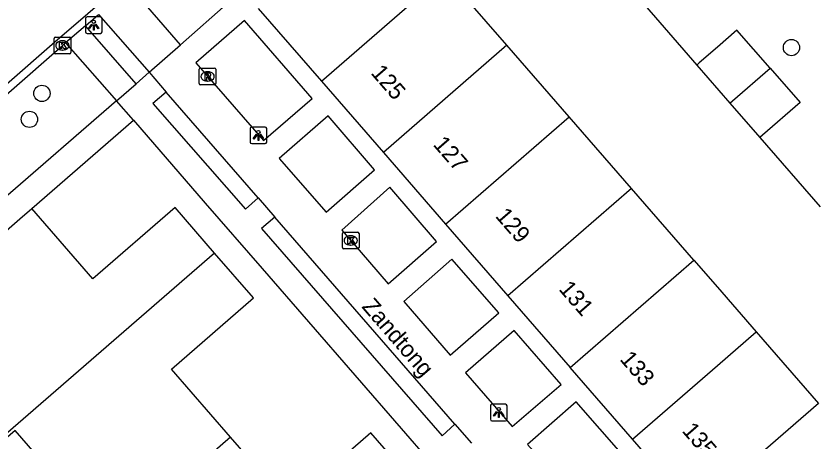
# Model space of a CAD drawing. Extents: x 155888 to 156864, y 383882 to 384671.
# Drawn here: x 156457.85 to 156505.75, y 384320.29 to 384345.85 of the extents above; entities that cross this region are included whole.
import ezdxf

# ---------------------------------------------------------------- set-up
doc = ezdxf.new("R2010")
doc.units = 0
for name, color, linetype in [('IMGEO_Boom', 7, 'Continuous'), ('IMGEO_Kolk', 7, 'Continuous'), ('IMGEO_Lichtpunt', 7, 'Continuous'), ('IMGEO_Muur', 7, 'Continuous'), ('IMGEO_Openbare_ruimte_label', 7, 'Continuous'), ('IMGEO_Pand', 7, 'Continuous'), ('IMGEO_Pand_nummerreeks', 7, 'Continuous'), ('IMGEO_Rijbaan_lokaal_gesloten', 7, 'Continuous'), ('IMGEO_Rijbaan_lokaal_open', 7, 'Continuous'), ('IMGEO_Rioolput', 7, 'Continuous'), ('IMGEO_Voetpad_open', 7, 'Continuous')]:
    doc.layers.add(name, color=color, linetype=linetype)

msp = doc.modelspace()

# ---------------------------------------------------------------- linework, layer by layer
at = {"layer": 'IMGEO_Boom'}
for centre in [(156504.451, 384343.944), (156459.411, 384341.19), (156458.663, 384339.629)]:
    msp.add_circle(centre, 0.489, dxfattribs=at)
at = {"layer": 'IMGEO_Kolk'}
for p, q in [((156460.144, 384343.644), (156460.144, 384344.496)), ((156460.219, 384344.57), (156461.071, 384344.57)), ((156461.145, 384344.496), (156461.145, 384343.644)), ((156460.632, 384344.35), (156460.657, 384344.35)), ((156461.071, 384343.57), (156460.219, 384343.57)), ((156460.655, 384343.79), (156460.63, 384343.79)), ((156477.465, 384331.921), (156477.465, 384332.773)), ((156477.54, 384332.847), (156478.392, 384332.847)), ((156477.953, 384332.627), (156477.978, 384332.627)), ((156478.466, 384332.773), (156478.466, 384331.921)), ((156477.976, 384332.067), (156477.951, 384332.067)), ((156478.392, 384331.847), (156477.54, 384331.847))]:
    msp.add_line(p, q, dxfattribs=at)
for points in [[(156460.144, 384343.644), (156460.144, 384344.496)], [(156460.219, 384344.57), (156461.071, 384344.57)], [(156461.145, 384344.496), (156461.145, 384343.644)], [(156460.465, 384344.27), (156460.588, 384344.27), (156460.588, 384344.119), (156460.718, 384344.27), (156460.882, 384344.27), (156460.736, 384344.119), (156460.889, 384343.87), (156460.737, 384343.87), (156460.652, 384344.034), (156460.588, 384343.967), (156460.588, 384343.87), (156460.465, 384343.87), (156460.465, 384344.27)], [(156461.071, 384343.57), (156460.219, 384343.57)], [(156477.465, 384331.921), (156477.465, 384332.773)], [(156477.54, 384332.847), (156478.392, 384332.847)], [(156477.786, 384332.547), (156477.909, 384332.547), (156477.909, 384332.396), (156478.039, 384332.547), (156478.203, 384332.547), (156478.057, 384332.396), (156478.21, 384332.147), (156478.058, 384332.147), (156477.973, 384332.311), (156477.909, 384332.244), (156477.909, 384332.147), (156477.786, 384332.147), (156477.786, 384332.547)], [(156478.466, 384332.773), (156478.466, 384331.921)], [(156478.392, 384331.847), (156477.54, 384331.847)]]:
    msp.add_lwpolyline(points, dxfattribs=at)
for centre, start, end in [((156460.221, 384344.494), 91.552, 178.448), ((156460.221, 384344.494), 91.552, 178.448), ((156461.069, 384344.494), 1.552, 88.448), ((156461.069, 384344.494), 1.552, 88.448), ((156460.221, 384343.646), 181.552, 268.448), ((156460.221, 384343.646), 181.552, 268.448), ((156461.069, 384343.646), 271.552, 358.448), ((156461.069, 384343.646), 271.552, 358.448), ((156477.542, 384332.771), 91.552, 178.448), ((156477.542, 384332.771), 91.552, 178.448), ((156478.39, 384332.771), 1.552, 88.448), ((156478.39, 384332.771), 1.552, 88.448), ((156477.542, 384331.923), 181.552, 268.448), ((156477.542, 384331.923), 181.552, 268.448), ((156478.39, 384331.923), 271.552, 358.448), ((156478.39, 384331.923), 271.552, 358.448)]:
    msp.add_arc(centre, 0.0765, start, end, dxfattribs=at)
for centre, major_axis, ratio, start_param, end_param in [((156460.631, 384344.07), (-0.387, 0.002), 0.722429, 4.712389, 7.853982), ((156460.656, 384344.07), (-0.39, 0.002), 0.717154, 1.570796, 4.712389), ((156477.952, 384332.347), (-0.387, 0.002), 0.722429, 4.712389, 7.853982), ((156477.977, 384332.347), (-0.39, 0.002), 0.717154, 1.570796, 4.712389)]:
    msp.add_ellipse(centre, major_axis=major_axis, ratio=ratio, start_param=start_param, end_param=end_param, dxfattribs=at)
at = {"layer": 'IMGEO_Lichtpunt'}
for p, q in [((156462.028, 384345.694), (156462.028, 384344.887)), ((156462.028, 384345.694), (156462.028, 384344.887)), ((156462.93, 384345.789), (156462.122, 384345.789)), ((156462.93, 384345.789), (156462.122, 384345.789)), ((156463.024, 384344.887), (156463.024, 384345.694)), ((156463.024, 384344.887), (156463.024, 384345.694)), ((156462.122, 384344.793), (156462.93, 384344.793)), ((156462.122, 384344.793), (156462.93, 384344.793)), ((156472.825, 384339.163), (156472.017, 384339.163)), ((156472.825, 384339.163), (156472.017, 384339.163)), ((156471.923, 384339.068), (156471.923, 384338.261)), ((156471.923, 384339.068), (156471.923, 384338.261)), ((156472.919, 384338.261), (156472.919, 384339.068)), ((156472.919, 384338.261), (156472.919, 384339.068)), ((156472.017, 384338.167), (156472.825, 384338.167)), ((156472.017, 384338.167), (156472.825, 384338.167)), ((156486.361, 384322.407), (156486.361, 384321.6)), ((156486.361, 384322.407), (156486.361, 384321.6)), ((156487.263, 384322.502), (156486.455, 384322.502)), ((156487.263, 384322.502), (156486.455, 384322.502)), ((156487.357, 384321.6), (156487.357, 384322.407)), ((156487.357, 384321.6), (156487.357, 384322.407)), ((156486.455, 384321.506), (156487.263, 384321.506)), ((156486.455, 384321.506), (156487.263, 384321.506))]:
    msp.add_line(p, q, dxfattribs=at)
for points in [[(156462.402, 384345.358), (156462.441, 384345.33), (156462.253, 384345.068), (156462.215, 384345.095), (156462.402, 384345.358)], [(156462.614, 384345.33), (156462.652, 384345.357), (156462.839, 384345.095), (156462.8, 384345.067), (156462.614, 384345.33)], [(156462.504, 384345.31), (156462.551, 384345.31), (156462.551, 384344.988), (156462.504, 384344.988), (156462.504, 384345.31)], [(156472.297, 384338.732), (156472.336, 384338.704), (156472.148, 384338.442), (156472.11, 384338.469), (156472.297, 384338.732)], [(156472.399, 384338.684), (156472.446, 384338.684), (156472.446, 384338.362), (156472.399, 384338.362), (156472.399, 384338.684)], [(156472.509, 384338.704), (156472.547, 384338.731), (156472.734, 384338.469), (156472.695, 384338.441), (156472.509, 384338.704)], [(156486.735, 384322.071), (156486.774, 384322.043), (156486.586, 384321.781), (156486.548, 384321.808), (156486.735, 384322.071)], [(156486.837, 384322.023), (156486.884, 384322.023), (156486.884, 384321.701), (156486.837, 384321.701), (156486.837, 384322.023)], [(156486.947, 384322.043), (156486.985, 384322.07), (156487.172, 384321.808), (156487.133, 384321.78), (156486.947, 384322.043)]]:
    msp.add_lwpolyline(points, dxfattribs=at)
for centre in [(156462.527, 384345.492), (156472.422, 384338.866), (156486.86, 384322.205)]:
    msp.add_circle(centre, 0.0994, dxfattribs=at)
for centre, start, end in [((156462.122, 384345.694), 90, 180), ((156462.122, 384345.694), 90, 180), ((156462.93, 384345.694), 0, 90), ((156462.93, 384345.694), 0, 90), ((156462.122, 384344.887), 180, 270), ((156462.122, 384344.887), 180, 270), ((156462.93, 384344.887), 270, 0), ((156462.93, 384344.887), 270, 360), ((156472.017, 384339.068), 90, 180), ((156472.017, 384339.068), 90, 180), ((156472.825, 384339.068), 0, 90), ((156472.825, 384339.068), 0, 90), ((156472.017, 384338.261), 180, 270), ((156472.017, 384338.261), 180, 270), ((156472.825, 384338.261), 270, 0), ((156472.825, 384338.261), 270, 360), ((156486.455, 384322.407), 90, 180), ((156486.455, 384322.407), 90, 180), ((156487.263, 384322.407), 0, 90), ((156487.263, 384322.407), 0, 90), ((156486.455, 384321.6), 180, 270), ((156486.455, 384321.6), 180, 270), ((156487.263, 384321.6), 270, 0), ((156487.263, 384321.6), 270, 360)]:
    msp.add_arc(centre, 0.0946, start, end, dxfattribs=at)
at = {"layer": 'IMGEO_Muur'}
for points in [[(156458.808, 384334.27), (156464.905, 384339.571)], [(156464.905, 384339.571), (156469.23, 384334.581)], [(156472.638, 384330.653), (156480.994, 384321.034)]]:
    msp.add_lwpolyline(points, dxfattribs=at)
at = {"layer": 'IMGEO_Pand'}
for points in [[(156476.205, 384341.922), (156483.63, 384348.371)], [(156487.352, 384344.088), (156483.63, 384348.371)], [(156472.407, 384346.293), (156476.205, 384341.922)], [(156503.164, 384342.708), (156501.175, 384344.991), (156500, 384343.967), (156498.913, 384343.02), (156498.767, 384342.893)], [(156487.352, 384344.088), (156479.927, 384337.639)], [(156491.094, 384339.781), (156487.352, 384344.088)], [(156498.767, 384342.893), (156500.749, 384340.609)], [(156500.749, 384340.609), (156500.9, 384340.74), (156503.164, 384342.708)], [(156503.164, 384342.708), (156504.964, 384340.643), (156502.702, 384338.672), (156502.546, 384338.536)], [(156476.205, 384341.922), (156479.927, 384337.639)], [(156500.749, 384340.609), (156502.546, 384338.536)], [(156483.67, 384333.332), (156491.094, 384339.781)], [(156494.838, 384335.473), (156491.094, 384339.781)], [(156479.927, 384337.639), (156483.67, 384333.332)], [(156494.838, 384335.473), (156487.414, 384329.022)], [(156498.582, 384331.165), (156494.838, 384335.473)], [(156469.786, 384331.59), (156467.41, 384334.325), (156462.481, 384330.043), (156458.808, 384334.27)], [(156450.897, 384327.362), (156458.088, 384333.641), (156458.808, 384334.27)], [(156483.67, 384333.332), (156487.414, 384329.022)], [(156469.786, 384331.59), (156456.92, 384320.42)], [(156470.753, 384320.521), (156467.203, 384324.607), (156472.133, 384328.89), (156469.786, 384331.59)], [(156491.157, 384324.716), (156498.582, 384331.165)], [(156498.582, 384331.165), (156500, 384329.533), (156502.325, 384326.857)], [(156487.414, 384329.022), (156491.157, 384324.716)], [(156494.901, 384320.407), (156500, 384324.837), (156502.325, 384326.857)], [(156502.325, 384326.857), (156506.069, 384322.549)], [(156494.901, 384320.407), (156491.157, 384324.716)], [(156506.069, 384322.549), (156500, 384317.276), (156498.645, 384316.099)], [(156462.826, 384313.623), (156462.643, 384313.833), (156463.398, 384314.488), (156457.805, 384320.926), (156457.05, 384320.27), (156456.92, 384320.42)], [(156470.753, 384320.521), (156462.826, 384313.623)], [(156481.578, 384318.018), (156479.178, 384320.781), (156474.248, 384316.499), (156470.753, 384320.521)], [(156498.645, 384316.099), (156494.901, 384320.407)]]:
    msp.add_lwpolyline(points, dxfattribs=at)
at = {"layer": 'IMGEO_Rijbaan_lokaal_gesloten'}
msp.add_lwpolyline([(156466.597, 384349.82), (156461.728, 384345.598), (156460.345, 384344.417), (156453.722, 384338.62), (156444.208, 384330.292), (156436.91, 384323.995), (156406.345, 384297.398), (156405.149, 384296.413)], dxfattribs=at)
at = {"layer": 'IMGEO_Rijbaan_lokaal_open'}
for points in [[(156495.094, 384347.126), (156498.767, 384342.893)], [(156462.027, 384345.248), (156462.818, 384345.935)], [(156462.027, 384345.248), (156460.835, 384344.231)], [(156443.01, 384328.651), (156444.51, 384329.945), (156454.025, 384338.274), (156460.646, 384344.069), (156460.835, 384344.231)], [(156502.546, 384338.536), (156506.171, 384334.359)]]:
    msp.add_lwpolyline(points, dxfattribs=at)
at = {"layer": 'IMGEO_Rioolput'}
for p, q in [((156468.864, 384341.784), (156468.864, 384342.636)), ((156468.939, 384342.71), (156469.791, 384342.71)), ((156469.352, 384342.49), (156469.377, 384342.49)), ((156469.865, 384342.636), (156469.865, 384341.784)), ((156469.791, 384341.71), (156468.939, 384341.71)), ((156469.375, 384341.93), (156469.35, 384341.93))]:
    msp.add_line(p, q, dxfattribs=at)
for points in [[(156468.864, 384341.784), (156468.864, 384342.636)], [(156468.939, 384342.71), (156469.791, 384342.71)], [(156469.865, 384342.636), (156469.865, 384341.784)], [(156469.453, 384342.408), (156469.201, 384342.41), (156469.201, 384342.01)], [(156469.201, 384342.01), (156469.325, 384342.01), (156469.325, 384342.172), (156469.336, 384342.172)], [(156469.379, 384342.329), (156469.325, 384342.329), (156469.325, 384342.248)], [(156469.325, 384342.248), (156469.377, 384342.248)], [(156469.383, 384342.143), (156469.454, 384342.01), (156469.594, 384342.01), (156469.529, 384342.136)], [(156469.791, 384341.71), (156468.939, 384341.71)]]:
    msp.add_lwpolyline(points, dxfattribs=at)
for centre, radius, start, end in [((156468.941, 384342.634), 0.0765, 91.552, 178.448), ((156468.941, 384342.634), 0.0765, 91.552, 178.448), ((156469.789, 384342.634), 0.0765, 1.552, 88.448), ((156469.789, 384342.634), 0.0765, 1.552, 88.448), ((156469.335, 384342.119), 0.0533, 26.0293, 88.6989), ((156469.361, 384342.437), 0.19, 274.7715, 282.9687), ((156469.385, 384342.233), 0.0964, 77.0061, 93.1865), ((156469.399, 384342.29), 0.0378, 276.6634, 79.6772), ((156469.452, 384342.298), 0.109, 350.3612, 89.416), ((156469.45, 384342.298), 0.112, 277.5842, 350.9817), ((156469.434, 384342.083), 0.108, 29.5134, 73.7905), ((156468.941, 384341.786), 0.0765, 181.552, 268.448), ((156468.941, 384341.786), 0.0765, 181.552, 268.448), ((156469.789, 384341.786), 0.0765, 271.552, 358.448), ((156469.789, 384341.786), 0.0765, 271.552, 358.448)]:
    msp.add_arc(centre, radius, start, end, dxfattribs=at)
for centre, major_axis, ratio, start_param, end_param in [((156469.351, 384342.21), (-0.387, 0.002), 0.722429, 4.712389, 7.853982), ((156469.376, 384342.21), (-0.39, 0.002), 0.717154, 1.570796, 4.712389)]:
    msp.add_ellipse(centre, major_axis=major_axis, ratio=ratio, start_param=start_param, end_param=end_param, dxfattribs=at)
at = {"layer": 'IMGEO_Voetpad_open'}
for points in [[(156467.739, 384344.101), (156464.731, 384347.594)], [(156467.739, 384344.101), (156470.645, 384346.67)], [(156462.818, 384345.935), (156465.854, 384342.457)], [(156471.594, 384345.577), (156468.669, 384343.026), (156472.735, 384338.365), (156475.654, 384340.889), (156471.594, 384345.577)], [(156465.073, 384341.758), (156462.027, 384345.248)], [(156460.835, 384344.231), (156463.884, 384340.743)], [(156465.854, 384342.457), (156467.739, 384344.101)], [(156465.073, 384341.758), (156465.854, 384342.457)], [(156465.854, 384342.457), (156466.874, 384341.271)], [(156463.884, 384340.743), (156465.073, 384341.758)], [(156466.874, 384341.271), (156466.078, 384340.585), (156471.641, 384334.231), (156472.411, 384334.902)], [(156472.411, 384334.902), (156466.874, 384341.271)], [(156463.884, 384340.743), (156457.059, 384334.814), (156446.013, 384325.218)], [(156464.905, 384339.571), (156463.884, 384340.743)], [(156476.602, 384339.838), (156473.669, 384337.279), (156476.495, 384334.047), (156479.391, 384336.586), (156476.602, 384339.838)], [(156458.808, 384334.27), (156464.905, 384339.571)], [(156464.905, 384339.571), (156469.23, 384334.581), (156472.638, 384330.653), (156480.994, 384321.034), (156484.401, 384317.105), (156488.759, 384312.092)], [(156480.326, 384335.549), (156477.423, 384332.964), (156477.965, 384332.346), (156480.215, 384329.732), (156483.122, 384332.289), (156480.326, 384335.549)], [(156472.411, 384334.902), (156473.408, 384333.746)], [(156473.408, 384333.746), (156472.611, 384333.058), (156483.452, 384320.601), (156484.216, 384321.296)], [(156484.216, 384321.296), (156473.408, 384333.746)], [(156484.046, 384331.232), (156481.152, 384328.679), (156483.951, 384325.447), (156486.864, 384327.995), (156484.046, 384331.232)], [(156487.797, 384326.936), (156484.865, 384324.387), (156487.671, 384321.157), (156490.602, 384323.688), (156487.797, 384326.936)], [(156491.518, 384322.638), (156488.594, 384320.081), (156490.602, 384317.82), (156491.482, 384316.815), (156494.352, 384319.406), (156491.518, 384322.638)], [(156484.216, 384321.296), (156485.228, 384320.167)]]:
    msp.add_lwpolyline(points, dxfattribs=at)

# ---------------------------------------------------------------- texts
at = {"layer": 'IMGEO_Openbare_ruimte_label'}
msp.add_text('Zandtong', height=1, rotation=310.7816, dxfattribs=at).set_placement((156478.592, 384328.343))
at = {"layer": 'IMGEO_Pand_nummerreeks'}
for s, p in [('125', (156479.133, 384342.395)), ('127', (156482.872, 384338.092)), ('129', (156486.612, 384333.789)), ('131', (156490.425, 384329.399)), ('133', (156494.091, 384325.182)), ('135', (156497.83, 384320.879))]:
    msp.add_text(s, height=1, rotation=310.9894, dxfattribs=at).set_placement(p)

doc.saveas('drawing.dxf')
